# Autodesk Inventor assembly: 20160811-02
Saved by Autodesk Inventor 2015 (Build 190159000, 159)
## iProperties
Created: 2016-08
Part Number: 20160811-02
Document SubType Name: Assembly
Designer: navara
Author: navara
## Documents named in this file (3)
- D:\20160811\20160811-02_FIXED.iam
- D:\20160811\20160811-02_FIXED.ipt
- D:\20160811\20160811-03_FIXED.ipt
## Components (3 placed, 2 different names)
1. 20160811-02_FIXED:1
2. 20160811-02_FIXED:2
3. 20160811-03_FIXED:1
